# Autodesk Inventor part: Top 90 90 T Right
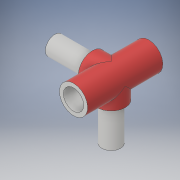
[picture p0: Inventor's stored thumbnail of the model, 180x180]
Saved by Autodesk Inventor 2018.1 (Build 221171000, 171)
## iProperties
Created: 2018-06
Part Number: Top 90 90 T Right
Material: Generic
Document SubType Name: Modeling
Designer: Ryan
Density: 1 g/cm^3
Appearance: Default
Author: Ryan
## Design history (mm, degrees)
derived "Assembly3 Part out.iam"
sketch "Sketch1"
  geometry: L1 (-38.527, 77.015)-(136.232, 77.015); L2 (136.232, 77.015)-(136.232, -217.058); L3 (136.232, -217.058)-(-38.527, -217.058); L4 (-38.527, -217.058)-(-38.527, 77.015); 1 further point
  constraints: 8 end point, 2 parallel, 1 horizontal, 1 perpendicular
extrude "Extrusion1" cut sketch "Sketch1" distance "d1" = 25.4; taper "d2" = 0 deg
workplane "Work Plane2"
  workplane "Work Plane1"
workpoint "Work Point1"
workplane "Work Plane3"
workplane "Work Plane4"
workplane "Work Plane5"
workplane "Work Plane6"
workplane "Work Plane7"
workplane "Work Plane8"
workplane "Work Plane9"
workplane "Work Plane10"
workplane "Work Plane11"
workplane "Work Plane12"
sketch "Sketch2"
  geometry: L1 (-186.77, 38.249)-(76.849, 38.249); L2 (76.849, 38.249)-(76.849, -126.593); L3 (76.849, -126.593)-(-186.77, -126.593); L4 (-186.77, -126.593)-(-186.77, 38.249); 1 further point
  constraints: 8 end point, 2 parallel, 1 horizontal, 1 perpendicular
extrude "Extrusion2" cut sketch "Sketch2" distance "d10" = 255.5875; taper "d11" = 0 deg
sketch "Sketch3"
  geometry: L1 (-118.781, 34.401)-(30.026, 34.401); L2 (30.026, 34.401)-(30.026, -118.896); L3 (30.026, -118.896)-(-118.781, -118.896); L4 (-118.781, -118.896)-(-118.781, 34.401); 1 further point
  constraints: 8 end point, 2 parallel, 1 horizontal, 1 perpendicular
extrude "Extrusion3" cut sketch "Sketch3" distance "d12" = 255.5875; taper "d13" = 0 deg
sketch "Sketch4"
  geometry: L1 (218.809, 34.128)-(50.76, 34.128); L2 (50.76, 34.128)-(50.76, -112.113); L3 (50.76, -112.113)-(218.809, -112.113); L4 (218.809, -112.113)-(218.809, 34.128); 1 further point
  constraints: 8 end point, 2 parallel, 1 horizontal, 1 perpendicular
extrude "Extrusion4" cut sketch "Sketch4" stored distance "d14" = 255.5875; taper "d15" = 0 deg
sketch "Sketch5"
  geometry: L1 (-123.912, -23.452)-(16.556, -23.452); L2 (16.556, -23.452)-(16.556, 25.295); L3 (16.556, 25.295)-(-123.912, 25.295); L4 (-123.912, 25.295)-(-123.912, -23.452); 1 further point
  constraints: 8 end point, 2 parallel, 1 horizontal, 1 perpendicular
extrude "Extrusion5" cut sketch "Sketch5" distance "d16" = 255.5875; taper "d17" = 0 deg
sketch "Sketch6"
  geometry: C1 r 3.429 at (0, 0); C2 r 3.429 at (101.6, 0); A1 r 4.763 centre (0, 0) between (-4.762, 0) and (3.368, -3.368) reference; A2 r 4.762 centre (101.6, 0) between (98.232, -3.368) and (106.362, 0) reference; 1 further point
  constraints: 2 centre point, 2 coincident
  dimensions: "d18" = 6.858 diameter of C1; "d19" = 6.858 diameter of C2
extrude "Extrusion6" cut sketch "Sketch6" distance "d20" = 255.5875; taper "d21" = 0 deg
workplane "Work Plane13"
workplane "Work Plane14"
sketch "Sketch7"
  geometry: L1 (-14.927, 11.967)-(19.631, 11.967); L2 (19.631, 11.967)-(19.631, -10.679); L3 (19.631, -10.679)-(-14.927, -10.679); L4 (-14.927, -10.679)-(-14.927, 11.967); 1 further point
  constraints: 8 end point, 2 parallel, 1 horizontal, 1 perpendicular
extrude "Extrusion7" cut sketch "Sketch7" stored distance "d24" = 255.5875; taper "d25" = 0 deg
sketch "Sketch8"
  geometry: C1 r 4.763 at (0, 0) reference; C2 r 3.175 at (0, 0); 1 further point
  constraints: 1 centre point, 1 coincident
  dimensions: "d26" = 6.35 diameter of C2
extrude "Extrusion8" join sketch "Sketch8" distance "d27" = 12.7; taper "d28" = 0 deg
workplane "Work Plane15"
sketch "Sketch9"
  geometry: L1 (-11.824, 12.427)-(116.114, 12.427); L2 (116.114, 12.427)-(116.114, -14.631); L3 (116.114, -14.631)-(-11.824, -14.631); L4 (-11.824, -14.631)-(-11.824, 12.427); 1 further point
  constraints: 8 end point, 2 parallel, 1 horizontal, 1 perpendicular
extrude "Extrusion9" cut sketch "Sketch9" distance "d30" = 12.7; taper "d31" = 0 deg
sketch "Sketch10"
  geometry: L1 (0, 0)-(4.762, -4.762) reference; C1 r 3.175 at (0, 0); C2 r 3.175 at (101.6, 0); A1 r 4.762 centre (101.6, 0) between (98.232, -3.368) and (106.362, 0) reference; 2 further points
  constraints: 2 centre point, 1 coincident
  dimensions: "d32" = 6.35 diameter of C1; "d33" = 6.35 diameter of C2
extrude "Extrusion10" join sketch "Sketch10" distance "d34" = 12.7; taper "d35" = 0 deg
sketch "Sketch11"
  geometry: C1 r 4.763 at (0, 0) reference; C2 r 3.175 at (0, 0); 1 further point
  constraints: 1 centre point, 1 coincident
  dimensions: "d36" = 6.35 diameter of C2
extrude "Extrusion11" join sketch "Sketch11" distance "d37" = 12.7; taper "d38" = 0 deg
sketch "Sketch12"
  geometry: L1 (15.212, 12.082)-(-15.369, 12.082); L2 (-15.369, 12.082)-(-15.369, -25.4); L3 (-15.369, -25.4)-(15.212, -25.4); L4 (15.212, -25.4)-(15.212, 12.082); 1 further point
  constraints: 8 end point, 2 parallel, 1 horizontal, 1 perpendicular
extrude "Extrusion12" cut sketch "Sketch12" distance "d39" = 103.1875; taper "d40" = 0 deg
body "Solid1"
node "Rov v4.2.ipt:1" dims "d0" = 10
node "Motor mount.ipt:1" dims "d0" = 10
node "Motor mount.ipt:2" dims "d0" = 10
node "Motor mount_MIR2.ipt:1" dims "d0" = 10
other parameters: "d3" = 12.7, "d4" = 12.7, "d5" = -12.7, "d6" = 12.7, "d7" = -12.7, "d8" = 12.7, "d9" = -12.7, "d22" = -6.35, "d23" = -6.35, "d29" = -6.35
